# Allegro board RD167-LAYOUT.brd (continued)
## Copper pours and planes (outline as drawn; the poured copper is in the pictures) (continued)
N17117438 on BOTTOM: 231.65,121.5 231.54,121.54 231.5,121.65 231.5,128.5 230.75,129.25 227.75,129.25 226.29,127.79 226.25,127.76 226.19,127.75 225.15,127.75 225.04,127.79 225,127.9 225,130.5 224.5,131 223.65,131 223.54,131.04 223.5,131.15 223.5,131.35 223.54,131.46 223.65,131.5 225,131.5 225.74,131.82 226.04,132.7 226.15,132.75 236.44,132.75 236.5,132.74 236.54,132.71 237.21,132.04 237.24,132 237.25,131.94 237.25,130.79 237.24,130.73 237.21,130.68 236.79,130.27 236.75,130.24 236.69,130.22 236.2,130.22 235.69,130.14 235.2,129.86 235.15,129.85 235.08,129.85 234.76,129.54 234.47,129.2 234.22,128.87 234,128.51 233.98,128.48 233,127.5 233,122.75 233.46,122.29 233.49,122.25 233.5,122.19 233.5,121.73 233.49,121.67 233.46,121.62 233.38,121.54 233.33,121.51 233.27,121.5
N17391340 on TOP: 212.85,257.75 212.76,257.77 212.68,257.82 211.07,259.43 211.02,259.51 211,259.6 211,260 211.02,260.09 211.07,260.17 211.73,260.83 211.81,260.88 211.9,260.9 212.17,260.9 212.26,260.88 212.34,260.83 213.59,259.59 214.17,259.18 214.87,259 215.03,258.93 215.1,258.75 215.1,258 215.03,257.82 214.85,257.75
N17392260 on TOP: 212.85,219.75 212.76,219.77 212.68,219.82 211.07,221.43 211.02,221.51 211,221.6 211,222 211.02,222.09 211.07,222.17 211.73,222.83 211.81,222.88 211.9,222.9 212.17,222.9 212.26,222.88 212.34,222.83 213.59,221.59 214.17,221.18 214.87,221 215.03,220.93 215.1,220.75 215.1,220 215.03,219.82 214.85,219.75
N17393142 on TOP: 212.85,169.75 212.76,169.77 212.68,169.82 211.07,171.43 211.02,171.51 211,171.6 211,172 211.02,172.09 211.07,172.17 211.73,172.83 211.81,172.88 211.9,172.9 212.17,172.9 212.26,172.88 212.34,172.83 213.59,171.59 214.17,171.18 214.87,171 215.03,170.93 215.1,170.75 215.1,170 215.03,169.82 214.85,169.75
N17393515 on TOP: 212.85,131.75 212.76,131.77 212.68,131.82 211.07,133.43 211.02,133.51 211,133.6 211,134 211.02,134.09 211.07,134.17 211.73,134.83 211.81,134.88 211.9,134.9 212.17,134.9 212.26,134.88 212.34,134.83 213.59,133.59 214.17,133.18 214.87,133 215.03,132.93 215.1,132.75 215.1,132 215.03,131.82 214.85,131.75

Small or netless copper shapes (teardrops, artwork), in the pictures only: 588 on TOP, 761 on BOTTOM, 51 on CONDUCTIVE2, 41 on CONDUCTIVE3, 28 on CONDUCTIVE4, 74 on CONDUCTIVE5

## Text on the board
BOTTOM: L6 HSP0183-B00-0001A
Board Geometry/Soldermask Bottom: L6 SR    HSP0183-B00-0001A
TOP: L1 HSP0183-B00-0001A
Board Geometry/Soldermask Top: L1 SR    HSP0183-B00-0001A
Ref Des/Silkscreen Top: Tr+ | Tr- | L+ | L- | HV_DC_P | HV_DC_N | LV_DC_N | LV_DC_P | HSP0183-B00-0001A | - | +
CONDUCTIVE2: L2 HSP0183-B00-0001A
CONDUCTIVE3: L3 HSP0183-B00-0001A
CONDUCTIVE4: L4 HSP0183-B00-0001A
CONDUCTIVE5: L5 HSP0183-B00-0001A
PAGE_OUTLINE: 1 | 8 | TB3 | R1 | R2 | TB4 | C69 | C67 | C66 | C37 | C35 | C68 | C36 | C34 | C65 | C64 | C63 | C62 | C33 | C32 | C29 | C28 | R7 | R4 | D25 | D13 | D19 | D7 | IC9 | IC7 | IC5 | IC3 | C71 | R57 | C39 | R32 | C19 | R21 | C51 | R45 | 7 | PS3 | PS5 | PS2 | PS4 | CT1 | PS1 | D2 | R3 | IC19 | C168 | R155 | R153 | TP45 | R154 | R156 | C170 | C8 | TP57 | TP1 | D3 | 3 | CN1 | CN2 | 2 | TP44 | TP59 | C174 | CN3 | R159 | R160 | C173 | C175 | TP58 | TP42 | C171 | R158 | R157 | 4 | PS10 | CT2 | PS7 | PS8 | PS9 | PS6 | R162 | R163 | R165 | R166 | R168 | R169 | R171 | R172 | R68 | C85 | R80 | C105 | R92 | C117 | R104 | C137 | IC11 | IC13 | IC15 | IC17 | R70 | R82 | R94 | R106 | C126 | C127 | C128 | C129 | C94 | C95 | C96 | C97 | TB5 | C132 | C100 | C101 | C130 | C99 | C131 | C133 | C98 | TB6 | C5 | C2 | TB1 | C6 | C3 | TB2 | TP20 | TP19 | TP15 | TP14 | TP10 | TP9 | TP5 | TP4 | D14 | D26 | D20 | D8 | C72 | C52 | C20 | C40 | C7 | C4 | TP21 | TP16 | TP11 | TP6 | R58 | R46 | R33 | R22 | R56 | R44 | R34 | R20 | TP17 | TP12 | TP2 | TP7 | C70 | C50 | C38 | C18 | C73 | C53 | C41 | C21 | TP18 | TP13 | TP8 | TP3 | C11 | C74 | C54 | C42 | C22 | C10 | TP49 | TP55 | TP50 | TP48 | TP47 | C1 | TP43 | PS11 | IC1 | R133 | LED1 | R5 | CN4 | C158 | 14 | IC23 | C162 | L1 | C163 | IC24 | TP46 | C146 | C153 | TP51 | TP52 | TP53 | TP54 | TP56 | C155 | C82 | C102 | C134 | C114 | TP23 | TP28 | TP33 | TP38 | C83 | C103 | C115 | C135 | TP22 | TP27 | TP32 | TP37 | C86 | C106 | C118 | C138 | R161 | R164 | R167 | R170 | TP31 | TP36 | TP41 | TP26 | C149 | C152 | R69 | R93 | R81 | R105 | C116 | C84 | C104 | C136 | D31 | D37 | D43 | D49 | TP25 | TP29 | TP30 | TP34 | TP35 | TP39 | TP40 | TP24 | TB8 | C148 | C151 | TB7 | C147 | C150 | 60 | 59 | K2 | D | A3 | A1 | S | G | L1 SILK          HSP0183-B00-0001A
SYMBOL-1-BOTTOM: 1 | 20 | R62 | R50 | R38 | R26 | R63 | R39 | R51 | R60 | R48 | R36 | R24 | R27 | D29 | D28 | C79 | D23 | D22 | C59 | D11 | D10 | C27 | D17 | D16 | C47 | C81 | R176 | D30 | C61 | R175 | D24 | C31 | R173 | D12 | C49 | R174 | D18 | R10 | R11 | R12 | R13 | R14 | R19 | C16 | R47 | R59 | R35 | R23 | C17 | R9 | R8 | C15 | R18 | R16 | C12 | C13 | IC22 | IC21 | C172 | C159 | R129 | R123 | R122 | R120 | C154 | C160 | R71 | R83 | R95 | R107 | C161 | R132 | R124 | R125 | R126 | R127 | R128 | D36 | C92 | D42 | D48 | D54 | R179 | R177 | R178 | C112 | C124 | R180 | C144 | C90 | D35 | D34 | C110 | D41 | D40 | C122 | D47 | D46 | C142 | D53 | D52 | R88 | R76 | R72 | R84 | R100 | R96 | R112 | R108 | R74 | R86 | R98 | R110 | K2 | D | S | Q3 | Q2 | D62 | Q4 | D61 | D60 | G | Q1 | D59 | A3 | A1 | C78 | C58 | C46 | C26 | R41 | R29 | R65 | R53 | D27 | D21 | D15 | D9 | R61 | R49 | R37 | R25 | R67 | R43 | R55 | R31 | R42 | R66 | R54 | R30 | C55 | C43 | C75 | C44 | C23 | C56 | C24 | C76 | 16 | IC10 | IC8 | IC6 | IC4 | R15 | C77 | C57 | C45 | C25 | C14 | R64 | R52 | R40 | R28 | R17 | D5 | D6 | IC2 | 8 | R138 | C165 | C164 | R134 | R139 | R135 | R140 | R144 | R136 | R141 | R137 | R142 | C167 | R145 | C166 | R143 | IC20 | D58 | D56 | R130 | R75 | R87 | R99 | R111 | C157 | C87 | C107 | C119 | C139 | R131 | IC12 | IC14 | IC16 | IC18 | C88 | C108 | C120 | C140 | C89 | C109 | C121 | C141 | R77 | R89 | R101 | R113 | R78 | R90 | R102 | R114 | R73 | R85 | R97 | R109 | D33 | D45 | D51 | D39 | R79 | R91 | R103 | R115 | C91 | C111 | C123 | C143 | D66 | D63 | Q6 | D64 | Q7 | D65 | Q8 | Q5 | L6 SILK          HSP0183-B00-0001A
User.5: L1 METAL HSP0183-B00-0001A
User.6: L6 METAL HSP0183-B00-0001A
